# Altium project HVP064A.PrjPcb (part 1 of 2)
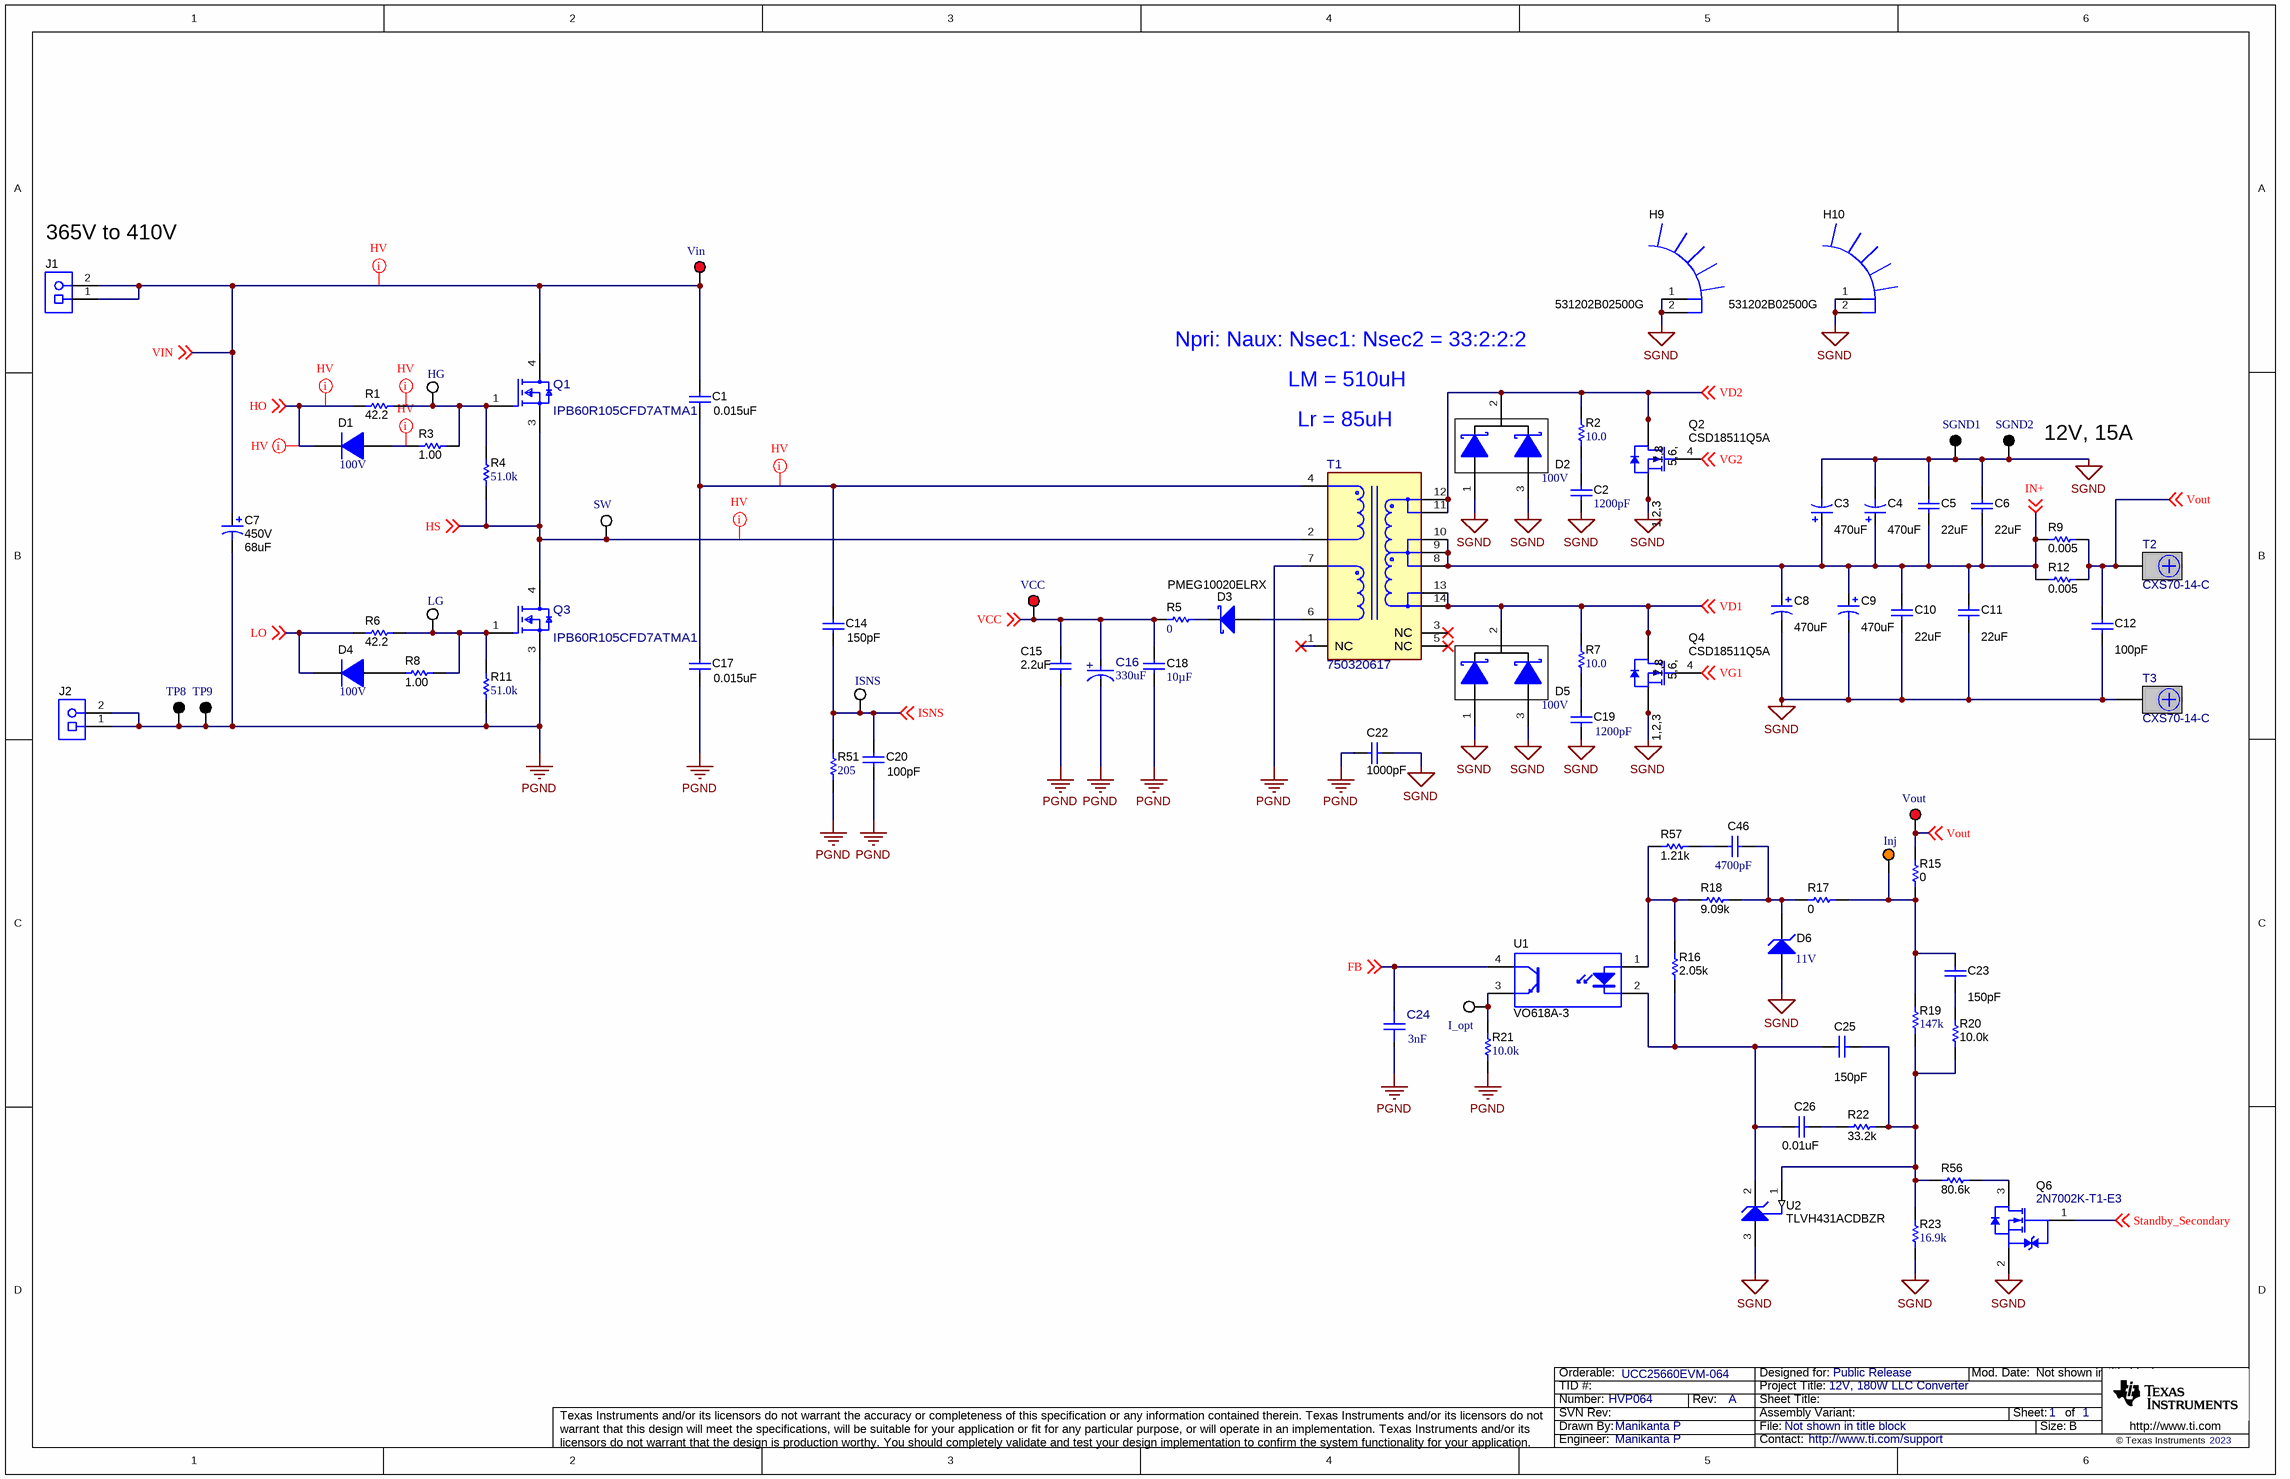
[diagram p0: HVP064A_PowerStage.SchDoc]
CopyrightYear: 2023; EVM_orderable: UCC25660EVM-064; PCB_Layout: Manikanta P; PCB_Rev: A; PRJ_Customer: Public Release; PRJ_Engineer: Manikanta P; PRJ_Number: HVP064; PRJ_Title: 12V, 180W LLC Converter; SCH_Rev: A; TechSupport: http://www.ti.com/support
3 sheets, 181 parts. Net scope: global (net labels, ports and power ports of the same name join across sheets).
Board file: HVP064A_PCB.PcbDoc
Sheets:
  HVP064A_PowerStage.SchDoc
  HVP064A_Control.SchDoc
  HVP064A_EVM_Hardware.SchDoc

## Sheet HVP064A_PowerStage.SchDoc
size 431 x 279 mm; EVM_orderable: UCC25660EVM-064; Date: Not shown in title block; ApprovedBy: Not shown in title block; CheckedBy: Not shown in title block; Author: Not shown in title block; CompanyName: Not shown in title block; DrawnBy: Manikanta P; Engineer: Not shown in title block; Organization: Not shown in title block; Address1: Not shown in title block; Address2: Not shown in title block; Address3: Not shown in title block; Address4: Not shown in title block; DocumentNumber: 1; Revision: Use project parameter SCH_Rev; SheetNumber: 1; SheetTotal: 1; PageSetup: Record=PageOptions¦CenterHorizontal=True¦CenterVertical=True¦PrintScale=1.00¦XCorrection=1.00¦YCorrection=1.00¦PrintKind=0¦BorderSize=5000000¦LeftOffset=0¦BottomOffset=0¦Orientation=2¦PaperLength=1000¦PaperWidth=1000¦Scale=100¦PaperSource=15¦PrintQuality=600¦MediaType=1¦DitherType=10¦PaperKind=Letter¦PrintScaleMode=1

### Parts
C1  ValueDisplayed: 0.015uF  [B32652_1800x700x1250]  (hidden comment: B32652A7153J000)
C2  ValueDisplayed: 1200pF  [0805L]  (hidden comment: GRM2165C2A122JA01D)
C3  ValueDisplayed: 470uF  [HW_1000x1600]  (hidden comment: UHW1V471MPD)
C4  ValueDisplayed: 470uF  [HW_1000x1600]  (hidden comment: UHW1V471MPD)
C5  ValueDisplayed: 22uF  [1206_190L]  (hidden comment: C3216X5R1E226M160AB)
C6  ValueDisplayed: 22uF  [1206_190L]  (hidden comment: C3216X5R1E226M160AB)
C7  VDC_V: 450V  ValueDisplayed: 68uF  [KXG_1800x3150]  (hidden comment: EKXG451ELL680MMN3S)
C8  ValueDisplayed: 470uF  [HW_1000x1600]  (hidden comment: UHW1V471MPD)
C9  ValueDisplayed: 470uF  [HW_1000x1600]  (hidden comment: UHW1V471MPD)
C10  ValueDisplayed: 22uF  [1206_190L]  (hidden comment: C3216X5R1E226M160AB)
C11  ValueDisplayed: 22uF  [1206_190L]  (hidden comment: C3216X5R1E226M160AB)
C12  ValueDisplayed: 100pF  [0603L]  (hidden comment: 06035A101FAT2A)
C14  ValueDisplayed: 150pF  [1206L]  (hidden comment: GRM31A5C2J151JW01D)
C15  ValueDisplayed: 2.2uF  [0805L]  (hidden comment: C2012X7R1V225K085AC)
C16  ValueDisplayed: 330uF  [FP-35ZL330MEFC10X16_RADIAL-MFG]  (hidden comment: 35ZL330MEFC10X16)
C17  ValueDisplayed: 0.015uF  [B32652_1800x700x1250]  (hidden comment: B32652A7153J000)
C18  ValueDisplayed: 10µF  [1206_180]  (hidden comment: C1206C106J3RACAUTO)
C19  ValueDisplayed: 1200pF  [0805L]  (hidden comment: GRM2165C2A122JA01D)
C20  ValueDisplayed: 100pF  [1206L]  (hidden comment: 12061A101JAT2A)
C22  ValueDisplayed: 1000pF  [CD45_700x600x1100]  (hidden comment: CD45-E2GA102M-NKA)
C23  ValueDisplayed: 150pF  [0402L]  (hidden comment: 885012005062)
C24  ValueDisplayed: 3nF  [FP-C1206C302J5GACTU_1206-MFG]  (hidden comment: C1206C302J5GACTU)
C25  ValueDisplayed: 150pF  [0402L]  (hidden comment: 885012005062)
C26  ValueDisplayed: 0.01uF  [0603L]  (hidden comment: 06031C103JAT2A)
C46  ValueDisplayed: 4700pF  [0603L]  (hidden comment: C0603C472J1GAC7867)
D1  Vr_V: 100V  [SOD-123]  (hidden comment: 1N4148W-7-F)
D2  Vr_V: 100V  [TO-220AB_100mil]  (hidden comment: STPS41H100CTY)
D3  PMEG10020ELRX  [SOD-123W]
D4  Vr_V: 100V  [SOD-123]  (hidden comment: 1N4148W-7-F)
D5  Vr_V: 100V  [TO-220AB_100mil]  (hidden comment: STPS41H100CTY)
D6  Vz_V: 11V  [SMA]  (hidden comment: 1SMA5926BT3G)
H9  531202B02500G  [531202]
H10  531202B02500G  [531202]
HG  5012  [Keystone5012]  (value not drawn)
I_opt  5012  [Keystone5012]  (value not drawn)
Inj  5013  [Keystone5013]  (value not drawn)
ISNS  5012  [Keystone5012]  (value not drawn)
J1  ED120/2DS  [On-Shore_ED120_2DS]  (value not drawn)
J2  ED120/2DS  [On-Shore_ED120_2DS]  (value not drawn)
LG  5012  [Keystone5012]  (value not drawn)
Q1  IPB60R105CFD7ATMA1  [FP-IPB60R105CFD7ATMA1_D2PAK-MFG]
Q2  CSD18511Q5A  [DQJ0008A]
Q3  IPB60R105CFD7ATMA1  [FP-IPB60R105CFD7ATMA1_D2PAK-MFG]
Q4  CSD18511Q5A  [DQJ0008A]
Q6  2N7002K-T1-E3  [SOT-23L]
R1  ValueDisplayed: 42.2  [0603]  (hidden comment: RC0603FR-0742R2L)
R2  ValueDisplayed: 10.0  [1206L]  (hidden comment: RC1206FR-0710RL)
R3  ValueDisplayed: 1.00  [0603L]  (hidden comment: RC0603FR-071RL)
R4  ValueDisplayed: 51.0k  [0603L]  (hidden comment: RC0603FR-0751KL)
R5  ValueDisplayed: 0  [1206L]  (hidden comment: ERJ-8GEY0R00V)
R6  ValueDisplayed: 42.2  [0603L]  (hidden comment: RC0603FR-0742R2L)
R7  ValueDisplayed: 10.0  [1206L]  (hidden comment: RC1206FR-0710RL)
R8  ValueDisplayed: 1.00  [0603L]  (hidden comment: RC0603FR-071RL)
R9  ValueDisplayed: 0.005  [2010L]  (hidden comment: CSNL2010FT5L00)
R11  ValueDisplayed: 51.0k  [0603L]  (hidden comment: RC0603FR-0751KL)
R12  ValueDisplayed: 0.005  [2010L]  (hidden comment: CSNL2010FT5L00)
R15  ValueDisplayed: 0  [0402L]  (hidden comment: RC0402JR-070RL)
R16  ValueDisplayed: 2.05k  [0603L]  (hidden comment: RC0603FR-072K05L)
R17  ValueDisplayed: 0  [1206L]  (hidden comment: CRCW12060000Z0EAHP)
R18  ValueDisplayed: 9.09k  [0603L]  (hidden comment: RC0603FR-079K09L)
R19  ValueDisplayed: 147k  [0603L]  (hidden comment: RC0603FR-07147KL)
R20  ValueDisplayed: 10.0k  [0603L]  (hidden comment: ERJ-3EKF1002V)
R21  ValueDisplayed: 10.0k  [0402L]  (hidden comment: ERJ-2RKF1002X)
R22  ValueDisplayed: 33.2k  [0603L]  (hidden comment: RC0603FR-0733K2L)
R23  ValueDisplayed: 16.9k  [0603L]  (hidden comment: RC0603FR-0716K9L)
R51  ValueDisplayed: 205  [1206]  (hidden comment: RC1206FR-07205RL)
R56  ValueDisplayed: 80.6k  [0603L]  (hidden comment: RC0603FR-0780K6L)
R57  ValueDisplayed: 1.21k  [0603L]  (hidden comment: RC0603FR-071K21L)
SGND1  5011  [Keystone5011]  (value not drawn)
SGND2  5011  [Keystone5011]  (value not drawn)
SW  5012  [Keystone5012]  (value not drawn)
T1  750320617  [FP-750320617_PTH_XFRMR_36MM5_43MM0-MFG]
T2  CXS70-14-C  [Panduit_CXS70-14-C]
T3  CXS70-14-C  [Panduit_CXS70-14-C]
TP8  5011  [Keystone5011]  (value not drawn)
TP9  5011  [Keystone5011]  (value not drawn)
U1  VO618A-3  [DIP-4]
U2  TLVH431ACDBZR  [DBZ0003A_N]
VCC  5010  [Keystone5010]  (value not drawn)
Vin  5010  [Keystone5010]  (value not drawn)
Vout  5010  [Keystone5010]  (value not drawn)

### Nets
PGND: C7.2(-) C15.2 C16.1(CATHODE) C17.2 C18.2 C20.2 C22.2 C24.2 J2.1 J2.2 Q3.3(Source) R11.1 R21.1 R51.1 T1.7 TP8.1 TP9.1
SGND: C2.2 C3.2(-) C4.2(-) C5.1 C6.1 C8.2(-) C9.2(-) C10.2 C11.2 C12.2 C19.2 C22.1 D2.1(A) D2.3(A) D5.1(A) D5.3(A) D6.2(A) H9.1 H9.2 H10.1 H10.2 Q2.1(S) Q2.2(S) Q2.3(S) Q4.1(S) Q4.2(S) Q4.3(S) Q6.2(S) R23.1 SGND1.1 SGND2.1 T3.1 U2.3(ANODE)
FB: C24.1 U1.4(C) ; off-sheet FB
HO: D1.1(K) R1.1 ; off-sheet HO
HS: Q1.3(Source) Q3.4(Drain) R4.1 SW.1 T1.2 ; off-sheet HS
IN+: C3.1(+) C4.1(+) C5.2 C6.2 C8.1(+) C9.1(+) C10.1 C11.1 R9.1 R12.1 T1.8 T1.9 T1.10 ; off-sheet IN+
ISNS: C14.2 C20.1 ISNS.1 R51.2 ; off-sheet ISNS
LO: D4.1(K) R6.1 ; off-sheet LO
Standby_Secondary: Q6.1(G) ; off-sheet Standby_Secondary
VCC: C15.1 C16.2(ANODE) C18.1 R5.1 VCC.1 ; off-sheet VCC
VD1: D5.2(K) Q4.5(D) Q4.6(D) Q4.7(D) Q4.8(D) Q4.9(D) R7.2 T1.13 T1.14 ; off-sheet VD1
VD2: D2.2(K) Q2.5(D) Q2.6(D) Q2.7(D) Q2.8(D) Q2.9(D) R2.2 T1.11 T1.12 ; off-sheet VD2
VG1: Q4.4(G) ; off-sheet VG1
VG2: Q2.4(G) ; off-sheet VG2
VIN: C1.1 C7.1(+) J1.1 J1.2 Q1.4(Drain) Vin.1 ; off-sheet VIN
Vout: C12.1 R9.2 R12.2 R15.2 T2.1 Vout.1 ; off-sheet Vout
NetC1_2: C1.2 C14.1 C17.1 T1.4
NetC2_1: C2.1 R2.1
NetC19_1: C19.1 R7.1
NetC23_1: C23.1 Inj.1 R15.1 R17.2 R19.2
NetC23_2: C23.2 R20.2
NetC25_1: C25.1 R19.1 R20.1 R22.1 R23.2 R56.1 U2.1(REF)
NetC25_2: C25.2 C26.2 R16.1 U1.2(K) U2.2(CATHODE)
NetC26_1: C26.1 R22.2
NetC46_1: C46.1 D6.1(K) R17.1 R18.2
NetC46_2: C46.2 R57.2
NetD1_2: D1.2(A) R3.1
NetD3_1: D3.1(K) R5.2
NetD3_2: D3.2(A) T1.6
NetD4_2: D4.2(A) R8.1
NetHG_1: HG.1 Q1.1(Gate) R1.2 R3.2 R4.2
NetI_opt_1: I_opt.1 R21.2 U1.3(E)
NetLG_1: LG.1 Q3.1(Gate) R6.2 R8.2 R11.2
NetQ6_3: Q6.3(D) R56.2
NetR16_2: R16.2 R18.1 R57.1 U1.1(A)

Not connected (* = marked no-connect by the designer): T1 1(NC)* 3(NC)* 5(NC)*

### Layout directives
net class HV: HO, HS, NetC1_2, NetD1_2, NetHG_1, VIN

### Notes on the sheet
- (near J1) 365V to 410V
- Npri: Naux: Nsec1: Nsec2 = 33:2:2:2
- Lr = 85uH
- LM = 510uH
- (near SGND2) 12V, 15A

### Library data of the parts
C1 C17 = CMP-0012346-3: CAP, Film, 0.015 uF, 1250 V, +/- 5%, AEC-Q200 Grade 3, TH; Manufacturer: TDK; TaMin_C: -55°C; Polarized: N; SizeAreaWB_mm2: 180; Value1: Unknown; TaMax_C: 100°C; SizeZ_mm: 12.5; SizeX_mm: 18; SizeY_mm: 7; Cap_Case: 18x7x12.5; Value2: 1250V; SizeArea_mm2: 126; CompType: Capacitor; AEC Qualified: Y; Cap_F: 15nF; VDC_V: 1.25kV; AEC Grade: 3; AEC Category: Q200
C2 C19 = CMP-0008098-2: CAP, CERM, 1200 pF, 100 V, +/- 5%, C0G/NP0, 0805; Manufacturer: MuRata; TaMin_C: -55°C; Polarized: N; SizeAreaWB_mm2: 6.75; Value1: Unknown; U/M: EA; Value: 1200pF; TaMax_C: 125°C; SizeZ_mm: 1.45; SizeX_mm: 2; SizeY_mm: 1.25; Cap_Case: 0805; Value2: 100V; SizeArea_mm2: 2.5; Cap_F: 1.2nF; AEC Category: Q200
C3 C4 C8 C9 = CMP-0010541-2: CAP, AL, 470 uF, 35 V, +/- 20%, 0.03 ohm, TH; Manufacturer: Nichicon; TaMin_C: -40°C; ESR_ohm: 0.03; Polarized: Y; SizeAreaWB_mm2: 144; U/M: EA; Value: 470uF; TaMax_C: 105°C; SizeZ_mm: 17.5; SizeX_mm: 10; Cap_Case: 10x16mm; Value2: 35V; SizeArea_mm2: 100; CompType: Capacitor; AEC Qualified: N; Cap_F: 470µF; IRMS_A: 2A; AEC Category: Q200
C5 C6 C10 C11 = CMP-0008654-2: CAP, CERM, 22 uF, 25 V, +/- 20%, X5R, 1206_190; Manufacturer: TDK; TaMin_C: -55°C; Polarized: N; SizeAreaWB_mm2: 10.92; Value1: Unknown; U/M: EA; Value: 22uF; TaMax_C: 85°C; SizeZ_mm: 1.9; SizeX_mm: 3.2; SizeY_mm: 1.6; Cap_Case: 1206; Value2: 25V; SizeArea_mm2: 5.12; CompType: Capacitor; Cap_F: 22µF; AEC Category: Q200
C7 = CMP-0010043-2: CAP, AL, 68 uF, 450 V, +/- 20%, TH; Manufacturer: Chemi-Con; TaMin_C: -25°C; Polarized: Y; SizeAreaWB_mm2: 400; Value1: Unknown; U/M: EA; Value: 68uF; TaMax_C: 105°C; SizeZ_mm: 33; SizeX_mm: 18; Cap_Case: 18x31.5mm; SizeArea_mm2: 324; CompType: Capacitor; Cap_F: 68µF; IRMS_A: 6.3dA; AEC Category: Q200
C12 = CMP-0006762-4: CAP, CERM, 100 pF, 50 V, +/- 1%, C0G/NP0, 0603; Manufacturer: AVX; TaMin_C: -55°C; Polarized: N; SizeAreaWB_mm2: 4.68; Value1: Unknown; U/M: EA; TaMax_C: 125°C; SizeZ_mm: 1; SizeX_mm: 1.6; SizeY_mm: 0.8; Cap_Case: 0603; Value2: 50V; SizeArea_mm2: 1.28; CompType: Capacitor; Value: 100pF; AEC Category: Q200
C14 = CMP-0008885-2: CAP, CERM, 150 pF, 630 V, +/- 5%, C0G/NP0, 1206; Manufacturer: MuRata; TaMin_C: -55°C; Polarized: N; SizeAreaWB_mm2: 10.92; Value1: Unknown; U/M: EA; Value: 150pF; TaMax_C: 125°C; SizeZ_mm: 1.35; SizeX_mm: 3.2; SizeY_mm: 1.6; Cap_Case: 1206; Value2: 630V; SizeArea_mm2: 5.12; CompType: Capacitor; AEC Category: Q200
C15 = CMP-0007883-2: CAP, CERM, 2.2 uF, 35 V, +/- 10%, X7R, 0805; Manufacturer: TDK; TaMin_C: -55°C; Polarized: N; SizeAreaWB_mm2: 6.75; Value1: Unknown; U/M: EA; Value: 2.2uF; TaMax_C: 125°C; SizeZ_mm: 1.45; SizeX_mm: 2; SizeY_mm: 1.25; Cap_Case: 0805; Value2: 35V; SizeArea_mm2: 2.5; CompType: Capacitor; Cap_F: 2.2µF; AEC Category: Q200
C16 = CMP-0098283-1: Cap Aluminum Lytic 330uF 35V 20% (10 X 16mm) Radial 5mm 1430mA 4000h 105C Bulk; Manufacturer: Rubycon; AEC Qualified: No; Cap_F: 330µF; IRMS_A: 1.43A; SizeZ_mm: 17.5mm; Dissipation Factor: 12%; Leakage Current: 115.5uA; Life: 4000Hours; Value: 330µF
C18 = CMP-0081062-1: CAP, CERM, 10 µF, 25 V,+/- 5%, X7R, AEC-Q200 Grade 1, 1206; Manufacturer: Kemet; TaMin_C: -55°C; Polarized: N; SizeAreaWB_mm2: 10.92; U/M: EA; Value: 10uF; TaMax_C: 125°C; SizeZ_mm: 1.8; SizeX_mm: 3.2; SizeY_mm: 1.6; Value2: 25V; SizeArea_mm2: 5.12; AEC Qualified: Y; AEC Grade: 1; AEC Category: Q200
C20 = CMP-0008462-2: CAP, CERM, 100 pF, 100 V, +/- 5%, C0G/NP0, 1206; Manufacturer: AVX; TaMin_C: -55°C; ESR_ohm: 7.01d; Polarized: N; SizeAreaWB_mm2: 10.92; Value1: 0.701 ohm; U/M: EA; Value: 100pF; TaMax_C: 125°C; SizeZ_mm: 1.35; SizeX_mm: 3.2; SizeY_mm: 1.6; Cap_Case: 1206; Value2: 100V; SizeArea_mm2: 5.12; CompType: Capacitor; AEC Category: Q200
C22 = CMP-0009595-2: CAP, CERM, 1000 pF,  V, +/- 20%, E, D7xT6mm; Manufacturer: TDK; TaMin_C: -25°C; Polarized: N; SizeAreaWB_mm2: 101.2; Value1: Unknown; U/M: EA; Value: 1000pF; TaMax_C: 125°C; SizeZ_mm: 11; SizeX_mm: 10.65; SizeY_mm: 6; Cap_Case: 7x6x11mm; SizeArea_mm2: 63.9; Cap_F: 1nF; AEC Category: Q200
C23 C25 = CMP-0064913-2: CAP, CERM, 150 pF, 50 V,+/- 5%, C0G/NP0, 0402; Manufacturer: Wurth Elektronik; TaMin_C: -55°C; Polarized: N; SizeAreaWB_mm2: 3; Value1: Unknown; U/M: EA; Value: 150pF; TaMax_C: 125°C; SizeZ_mm: 0.6; SizeX_mm: 1; SizeY_mm: 0.5; Cap_Case: 0402; Value2: 50V; CompType: Capacitor; AEC Category: Q200
C24 = CMP-0120451-1: C1206 3,000 pF C0G 5.00% 50 V; Manufacturer: KEMET; AEC Grade: Grade 0; AEC Qualified: Yes; Cap_F: 3pF; SizeZ_mm: 0.88mm; TempCo: 15%; Tolerance_%: 0.05%; VDC_V: 50V; Value: 3pF
C26 = CMP-0006726-4: CAP, CERM, 0.01 uF, 100 V, +/- 5%, X7R, 0603; Manufacturer: AVX; TaMin_C: -55°C; ESR_ohm: 0.098; Polarized: N; SizeAreaWB_mm2: 4.68; Value1: 0.098 ohm; U/M: EA; Value: 0.01uF; TaMax_C: 125°C; SizeZ_mm: 1; SizeX_mm: 1.6; SizeY_mm: 0.8; Cap_Case: 0603; Value2: 100V; SizeArea_mm2: 1.28; Cap_F: 10nF; AEC Category: Q200
C46 = CMP-0006941-4: CAP, CERM, 4700 pF, 100 V, +/- 5%, C0G/NP0, 0603; Manufacturer: Kemet; TaMin_C: -55°C; Polarized: N; SizeAreaWB_mm2: 4.68; Value1: Unknown; U/M: EA; Value: 4700pF; TaMax_C: 125°C; SizeZ_mm: 1; SizeX_mm: 1.6; SizeY_mm: 0.8; Cap_Case: 0603; Value2: 100V; SizeArea_mm2: 1.28; Cap_F: 4.7nF; AEC Category: Q200
D1 D4 = CMP-0029001-2: Diode, Ultrafast, 100 V, 0.15 A, SOD-123; Manufacturer: Diodes Inc.; Io_A: 150mA; Green_Lifecycle: Active; SizeAreaWB_mm2: 13.095; Green_REACh: Passed; Value1: 0.15A; TJmax_C: 150°C; Value: 100V; SizeZ_mm: 1.35; SizeX_mm: 3.85; SizeY_mm: 1.7; Vf_V: 1.25V; SizeArea_mm2: 6.545; AEC Category: Q101
D2 D5 = CMP-0028866-3: Diode, Schottky, 100 V, 20 A, AEC-Q101, TH; Manufacturer: STMicroelectronics; Io_A: 20A; Green_Lifecycle: Not Set; SizeAreaWB_mm2: 79.3; Green_REACh: Incomplete; TJmax_C: 175°C; Value: 100V; SizeZ_mm: 19.4; SizeX_mm: 10.2; SizeY_mm: 4.5; Vf_V: 800mV; Value2: 0.8V; SizeArea_mm2: 45.9; AEC Qualified: Y; AEC Category: Q101
D3 = CMP-0028977-2: Diode, Schottky, 100 V, 2 A, AEC-Q101, SOD-123W; Manufacturer: Nexperia; Io_A: 2A; SizeAreaWB_mm2: 12.15; Vr_V: 100V; TJmax_C: 175°C; Value: 100V; SizeZ_mm: 1; SizeX_mm: 3.5; SizeY_mm: 1.7; Vf_V: 830mV; Value2: 0.83V; SizeArea_mm2: 5.95; AEC Qualified: Y; AEC Category: Q101
D6 = CMP-0005522-4: Diode, Zener, 11 V, 1.5 W, SMA; Manufacturer: ON Semiconductor; Power_W: 1.5W; SizeAreaWB_mm2: 37.3428; RJA_CperW: 250; Value: 11V; SizeZ_mm: 2.87; SizeX_mm: 5.59; SizeY_mm: 2.92; SizeArea_mm2: 16.3228; AEC Category: Q101
H9 H10 = CMP-0004053-1: Manufacturer: Aavid; Note: footprint renamed from HSINK_531202B025B025 to 531202; CompType: Heat Sink
HG I_opt ISNS LG SW = CMP-0055149-2: Test Point, Multipurpose, White, TH; Manufacturer: Keystone Electronics; CNHeader: FALSE; Green_Lifecycle: Active; Green_REACh: Passed; ContactFinish: Silver; CT: TRUE
Inj = CMP-0055150-2: Test Point, Multipurpose, Orange, TH; Manufacturer: Keystone Electronics; CNHeader: FALSE; Green_Lifecycle: Active; Green_REACh: Passed; ContactFinish: Silver; CT: TRUE
J1 J2 = CMP-0074910-1: Terminal Block, 5.08 mm, 2x1, Brass, TH; Manufacturer: On-Shore Technology; Cert_VDE: Y; CNHeader: False; Current_A: 15A; Green_Lifecycle: Not Set; Shrouded: N; Gender: Female; Green_REACh: Incomplete; Voltage_V: 300V; Row_Count: 1; Pitch_mm: 5.08; CT: True
Q1 Q3 = CMP-0065576-1: Power Transistor MOSFET N-Channel Enhancement 600V 21A 3-Pin D2PAK T/R; Manufacturer: Infineon; AEC Qualified: No; QgTyp_nC: 42nC @ 10V; Rdson45_ohm: 89m; SizeZ_mm: 4.5mm; Vgs_V: 20V; ChMode: False; Input Capacitace At Vds: 1752pF @ 400V; Number Of Channels: 1; Power_W: 106W; Pulse Drain Current: 79A; Reverse Recovery Charge: 480nC; Reverse Recovery Time: 102ns; Rthja Max: 62°C/W; Standoff Height: 0.1mm; Threshold Vgs Max: 4.5V; Threshold Vgs Min: 3.5V; TJmax_C: +150°C; Turn Off Delay Time: 94ns; Turn On Delay Time: 25ns; Typ Forward Diode Voltage: 1V
Q2 Q4 = CMP-0000711-1: MOSFET, N-CH, 40 V, 100 A, DQJ0008A (VSONP-8); Alternate Manufacturer: None; Manufacturer: Texas Instruments; SizeZ_mm: 1.1; ChType: N; Value2: 63 nC; Value1: 0.003; VdsMax_V: 40V; SizeX_mm: 6; SizeY_mm: 4.9; Vgs_V: 20V; Value: 40V; Rdson45_ohm: 3.5m; SizeArea_mm2: 29.4; AEC Category: Q101; IdsMax_A: 100A; SizeAreaWB_mm2: 55.2; U/M: EA; QgTyp_nC: 63
Q6 = CMP-0000773-1: MOSFET, N-CH, 60 V, 0.3 A, SOT-23; Alternate Manufacturer: None; Manufacturer: Vishay-Siliconix; SizeZ_mm: 1.1; ChType: N; Value2: 0.4 nC; VdsMax_V: 60V; SizeX_mm: 2.5; SizeY_mm: 3; Vgs_V: 20V; Value: 60V; Rdson45_ohm: 4; SizeArea_mm2: 7.5; AEC Category: Q101; IdsMax_A: 300mA; SizeAreaWB_mm2: 14; U/M: EA; QgTyp_nC: 0.4
R1 R6 = CMP-0023107-5: RES, 42.2, 1%, 0.1 W, 0603; Manufacturer: Yageo; Power_W: 100mW; TempCo: 100 ppm/C; Value_Code: 42R2; Value: 42.2; EIA_Code: E96; SizeX_mm: 1.6; SizeY_mm: 0.8; SizeZ_mm: 1; Value2: 0.1W; SizeArea_mm2: 1.28; CompType: Resistor; AEC Qualified: N; VDC_V: 75V; AEC Category: Q200; SizeAreaWB_mm2: 4.68
R2 R7 = CMP-0017851-2: RES, 10.0, 1%, 0.25 W, 1206; Manufacturer: Yageo America; Power_W: 250mW; TempCo: 200 ppm/C; Value_Code: 10R0; U/M: EA; Value: 10.0; EIA_Code: E96; Res_ohm: 10; SizeX_mm: 3.2; SizeY_mm: 1.6; SizeZ_mm: 1.35; Value2: 0.25W; SizeArea_mm2: 5.12; VDC_V: 200V; AEC Category: Q200
R3 R8 = CMP-0022900-4: RES, 1.00, 1%, 0.1 W, 0603; Manufacturer: Yageo; Power_W: 100mW; TempCo: 200 ppm/C; Value_Code: 1R00; Value: 1.00; EIA_Code: E96; Res_ohm: 1; SizeX_mm: 1.6; SizeY_mm: 0.8; Value2: 0.1W; SizeArea_mm2: 1.28; CompType: Resistor; AEC Qualified: N; VDC_V: 75V; AEC Category: Q200; SizeAreaWB_mm2: 4.68
R4 R11 = CMP-0023167-5: RES, 51.0 k, 1%, 0.1 W, 0603; Manufacturer: Yageo; Power_W: 100mW; TempCo: 100 ppm/C; Value_Code: 51k0; Value: 51.0k; Res_ohm: 51k; SizeX_mm: 1.6; SizeY_mm: 0.8; SizeZ_mm: 1; Value2: 0.1W; SizeArea_mm2: 1.28; AEC Qualified: N; VDC_V: 75V; AEC Category: Q200; SizeAreaWB_mm2: 4.68
R5 = CMP-0018748-3: RES, 0, 5%, 0.25 W, AEC-Q200 Grade 0, 1206; Manufacturer: Panasonic; Power_W: 250mW; TempCo: 600 ppm/C; Value_Code: 0000; Value: 0; EIA_Code: E24; SizeX_mm: 3.2; SizeY_mm: 1.6; SizeZ_mm: 1.35; Value2: 0.25W; SizeArea_mm2: 5.12; AEC Qualified: Y; VDC_V: 200V; AEC Category: Q200; SizeAreaWB_mm2: 10.92
R9 R12 = CMP-0016512-2: RES, 0.005, 1%, 1.5 W, 2010; Manufacturer: Stackpole Electronics Inc; Power_W: 1.5W; TempCo: 50 ppm/C; Value_Code: 5L000; U/M: EA; Value: 0.005; EIA_Code: E96; Res_ohm: 5m; SizeX_mm: 5; SizeY_mm: 2.5; SizeZ_mm: 1.66; SizeArea_mm2: 12.5; CompType: Resistor; AEC Category: Q200
R15 = CMP-0027004-2: RES, 0, 5%, 0.063 W, 0402; Manufacturer: Yageo America; Power_W: 63mW; TempCo: 200 ppm/C; Value_Code: 0000; U/M: EA; Value: 0; EIA_Code: E24; SizeX_mm: 1; SizeY_mm: 0.5; SizeZ_mm: 0.6; Value2: 0.063W; CompType: Resistor; VDC_V: 50V; AEC Category: Q200
R16 = CMP-0022981-5: RES, 2.05 k, 1%, 0.1 W, 0603; Manufacturer: Yageo; Power_W: 100mW; TempCo: 100 ppm/C; Value_Code: 2k05; Value: 2.05k; EIA_Code: E96; SizeX_mm: 1.6; SizeY_mm: 0.8; SizeZ_mm: 1; Value2: 0.1W; SizeArea_mm2: 1.28; AEC Qualified: N; VDC_V: 75V; AEC Category: Q200; SizeAreaWB_mm2: 4.68
R17 = CMP-0086176-1: RES, 0, 0.75 W, AEC-Q200 Grade 0, 1206; Manufacturer: Vishay-Dale; Value: 0; SizeY_mm: 1.6; SizeX_mm: 3.2; Tolerance_%: 0%; SizeArea_mm2: 5.12; EIA_Code: E96; SizeAreaWB_mm2: 10.92; Power_W: 750mW; AEC Qualified: Y; SizeZ_mm: 1.35; Value2: 0.75W; AEC Category: Q200; VDC_V: 200V
R18 = CMP-0023332-5: RES, 9.09 k, 1%, 0.1 W, 0603; Manufacturer: Yageo; Power_W: 100mW; TempCo: 100 ppm/C; Value_Code: 9k09; Value: 9.09k; EIA_Code: E96; SizeX_mm: 1.6; SizeY_mm: 0.8; SizeZ_mm: 1; Value2: 0.1W; SizeArea_mm2: 1.28; AEC Qualified: N; VDC_V: 75V; AEC Category: Q200; SizeAreaWB_mm2: 4.68
R19 = CMP-0022800-4: RES, 147 k, 1%, 0.1 W, 0603; Manufacturer: Yageo; Power_W: 100mW; TempCo: 100 ppm/C; Value: 147k; EIA_Code: E96; SizeX_mm: 1.6; SizeY_mm: 0.8; SizeZ_mm: 1; Value2: 0.1W; SizeArea_mm2: 1.28; AEC Qualified: N; VDC_V: 75V; AEC Category: Q200; SizeAreaWB_mm2: 4.68
R20 = CMP-0022684-3: RES, 10.0 k, 1%, 0.1 W, 0603; Manufacturer: Panasonic; Power_W: 100mW; TempCo: 100 ppm/C; Value_Code: 10k0; U/M: EA; Value: 10.0k; EIA_Code: E96; Res_ohm: 10k; SizeX_mm: 1.6; SizeY_mm: 0.8; SizeZ_mm: 1; Value2: 0.1W; SizeArea_mm2: 1.28; CompType: Resistor; VDC_V: 75V; AEC Category: Q200
R21 = CMP-0026658-1: RES, 10.0 k, 1%, 0.1 W, 0402; Manufacturer: Panasonic; Power_W: 100mW; TempCo: 100 ppm/C; Value_Code: 10k0; U/M: EA; Value: 10.0k; EIA_Code: E96; Res_ohm: 10k; SizeX_mm: 1; SizeY_mm: 0.5; SizeZ_mm: 0.6; Value2: 0.1W; VDC_V: 50V; AEC Category: Q200
R22 = CMP-0023036-5: RES, 33.2 k, 1%, 0.1 W, 0603; Manufacturer: Yageo; Power_W: 100mW; TempCo: 100 ppm/C; Value_Code: 33k2; Value: 33.2k; EIA_Code: E96; SizeX_mm: 1.6; SizeY_mm: 0.8; SizeZ_mm: 1; Value2: 0.1W; SizeArea_mm2: 1.28; AEC Qualified: N; VDC_V: 75V; AEC Category: Q200; SizeAreaWB_mm2: 4.68
R23 = CMP-0022830-5: RES, 16.9 k, 1%, 0.1 W, 0603; Manufacturer: Yageo; Power_W: 100mW; TempCo: 100 ppm/C; Value_Code: 16k9; Value: 16.9k; EIA_Code: E96; SizeX_mm: 1.6; SizeY_mm: 0.8; SizeZ_mm: 1; Value2: 0.1W; SizeArea_mm2: 1.28; AEC Qualified: N; VDC_V: 75V; AEC Category: Q200; SizeAreaWB_mm2: 4.68
R51 = CMP-0018063-2: RES, 205, 1%, 0.25 W, 1206; Manufacturer: Yageo America; Power_W: 250mW; TempCo: 100 ppm/C; Value_Code: 205R; U/M: EA; Value: 205; EIA_Code: E96; SizeX_mm: 3.2; SizeY_mm: 1.6; SizeZ_mm: 1.35; Value2: 0.25W; SizeArea_mm2: 5.12; VDC_V: 200V; AEC Category: Q200
R56 = CMP-0023285-5: RES, 80.6 k, 1%, 0.1 W, 0603; Manufacturer: Yageo; Power_W: 100mW; TempCo: 100 ppm/C; Value_Code: 80k6; EIA_Code: E96; SizeX_mm: 1.6; SizeY_mm: 0.8; SizeZ_mm: 1; Value2: 0.1W; Value: 80.6k; SizeArea_mm2: 1.28; AEC Qualified: N; VDC_V: 75V; AEC Category: Q200; SizeAreaWB_mm2: 4.68
R57 = CMP-0022871-5: RES, 1.21 k, 1%, 0.1 W, 0603; Manufacturer: Yageo; Power_W: 100mW; TempCo: 100 ppm/C; Value_Code: 1k21; Value: 1.21k; EIA_Code: E96; SizeX_mm: 1.6; SizeY_mm: 0.8; SizeZ_mm: 1; Value2: 0.1W; SizeArea_mm2: 1.28; AEC Qualified: N; VDC_V: 75V; AEC Category: Q200; SizeAreaWB_mm2: 4.68
SGND1 SGND2 TP8 TP9 = CMP-0055148-2: Test Point, Multipurpose, Black, TH; Manufacturer: Keystone Electronics; CNHeader: FALSE; Green_Lifecycle: Active; Green_REACh: Passed; ContactFinish: Silver; CT: TRUE
T1 = CMP-0065589-1: TRANSFORMER-; Manufacturer: Wurth Electronics; DCR_ohm: 0.135; Ind_H: 510µH; Ns1toNp: 16.5:1; Rsec1_ohm: 5m; SizeZ_mm: 26.5mm; AEC Qualified: No; Frequency_Fixed: 60-130kHz; Voltage_Isolation_Vrms: 3kV
T2 T3 = CMP-0075010-2: Terminal 70A Lug; Manufacturer: Panduit; CNHeader: False; Green_Lifecycle: Not Set; Green_REACh: Incomplete; CompType: Screw Terminal
U1 = CMP-0083653-1: Optocoupler, 5.3 kV, 100-200% CTR, SMT; Manufacturer: Vishay-Semiconductor; CTR (Max): 200%; SizeAreaWB_mm2: 71.064; CTR (Min): 100%; SizeZ_mm: 5; SizeX_mm: 8.8; SizeY_mm: 4.58; SizeArea_mm2: 40.304; Voltage_Isolation_Vrms: 5.3kV
U2 = CMP-0033066-1: Low-Voltage Adjustable Precision Shunt Regulator, 129 ppm / degC, 80 mA, 0 to 70 degC, 3-pin SOT-23 (DBZ), Green (RoHS & no Sb/Br); Manufacturer: Texas Instruments; Min Iz for Regulation(uA): 80; VO Adj(Max)(V): 18; VO Adj(Min)(V): 1.24; Rating: Catalog; SubFamily: Shunt Voltage Reference; Temp Coeff(Max)(ppm/ degree C): 129
VCC Vin Vout = CMP-0055147-2: Test Point, Multipurpose, Red, TH; Manufacturer: Keystone Electronics; CNHeader: FALSE; Green_Lifecycle: Active; Green_REACh: Passed; ContactFinish: Silver; CT: TRUE

## Sheet HVP064A_Control.SchDoc
size 431 x 279 mm; Date: Not shown in title block; ApprovedBy: Not shown in title block; CheckedBy: Not shown in title block; Author: Not shown in title block; CompanyName: Not shown in title block; Engineer: Not shown in title block; Organization: Not shown in title block; Address1: Not shown in title block; Address2: Not shown in title block; Address3: Not shown in title block; Address4: Not shown in title block; DocumentNumber: 1; Revision: Use project parameter SCH_Rev; SheetNumber: 1; SheetTotal: 1; PageSetup: Record=PageOptions¦CenterHorizontal=True¦CenterVertical=True¦PrintScale=1.00¦XCorrection=1.00¦YCorrection=1.00¦PrintKind=0¦BorderSize=5000000¦LeftOffset=0¦BottomOffset=0¦Orientation=2¦PaperLength=1000¦PaperWidth=1000¦Scale=100¦PaperSource=15¦PrintQuality=600¦MediaType=1¦DitherType=10¦PaperKind=Letter¦PrintScaleMode=1
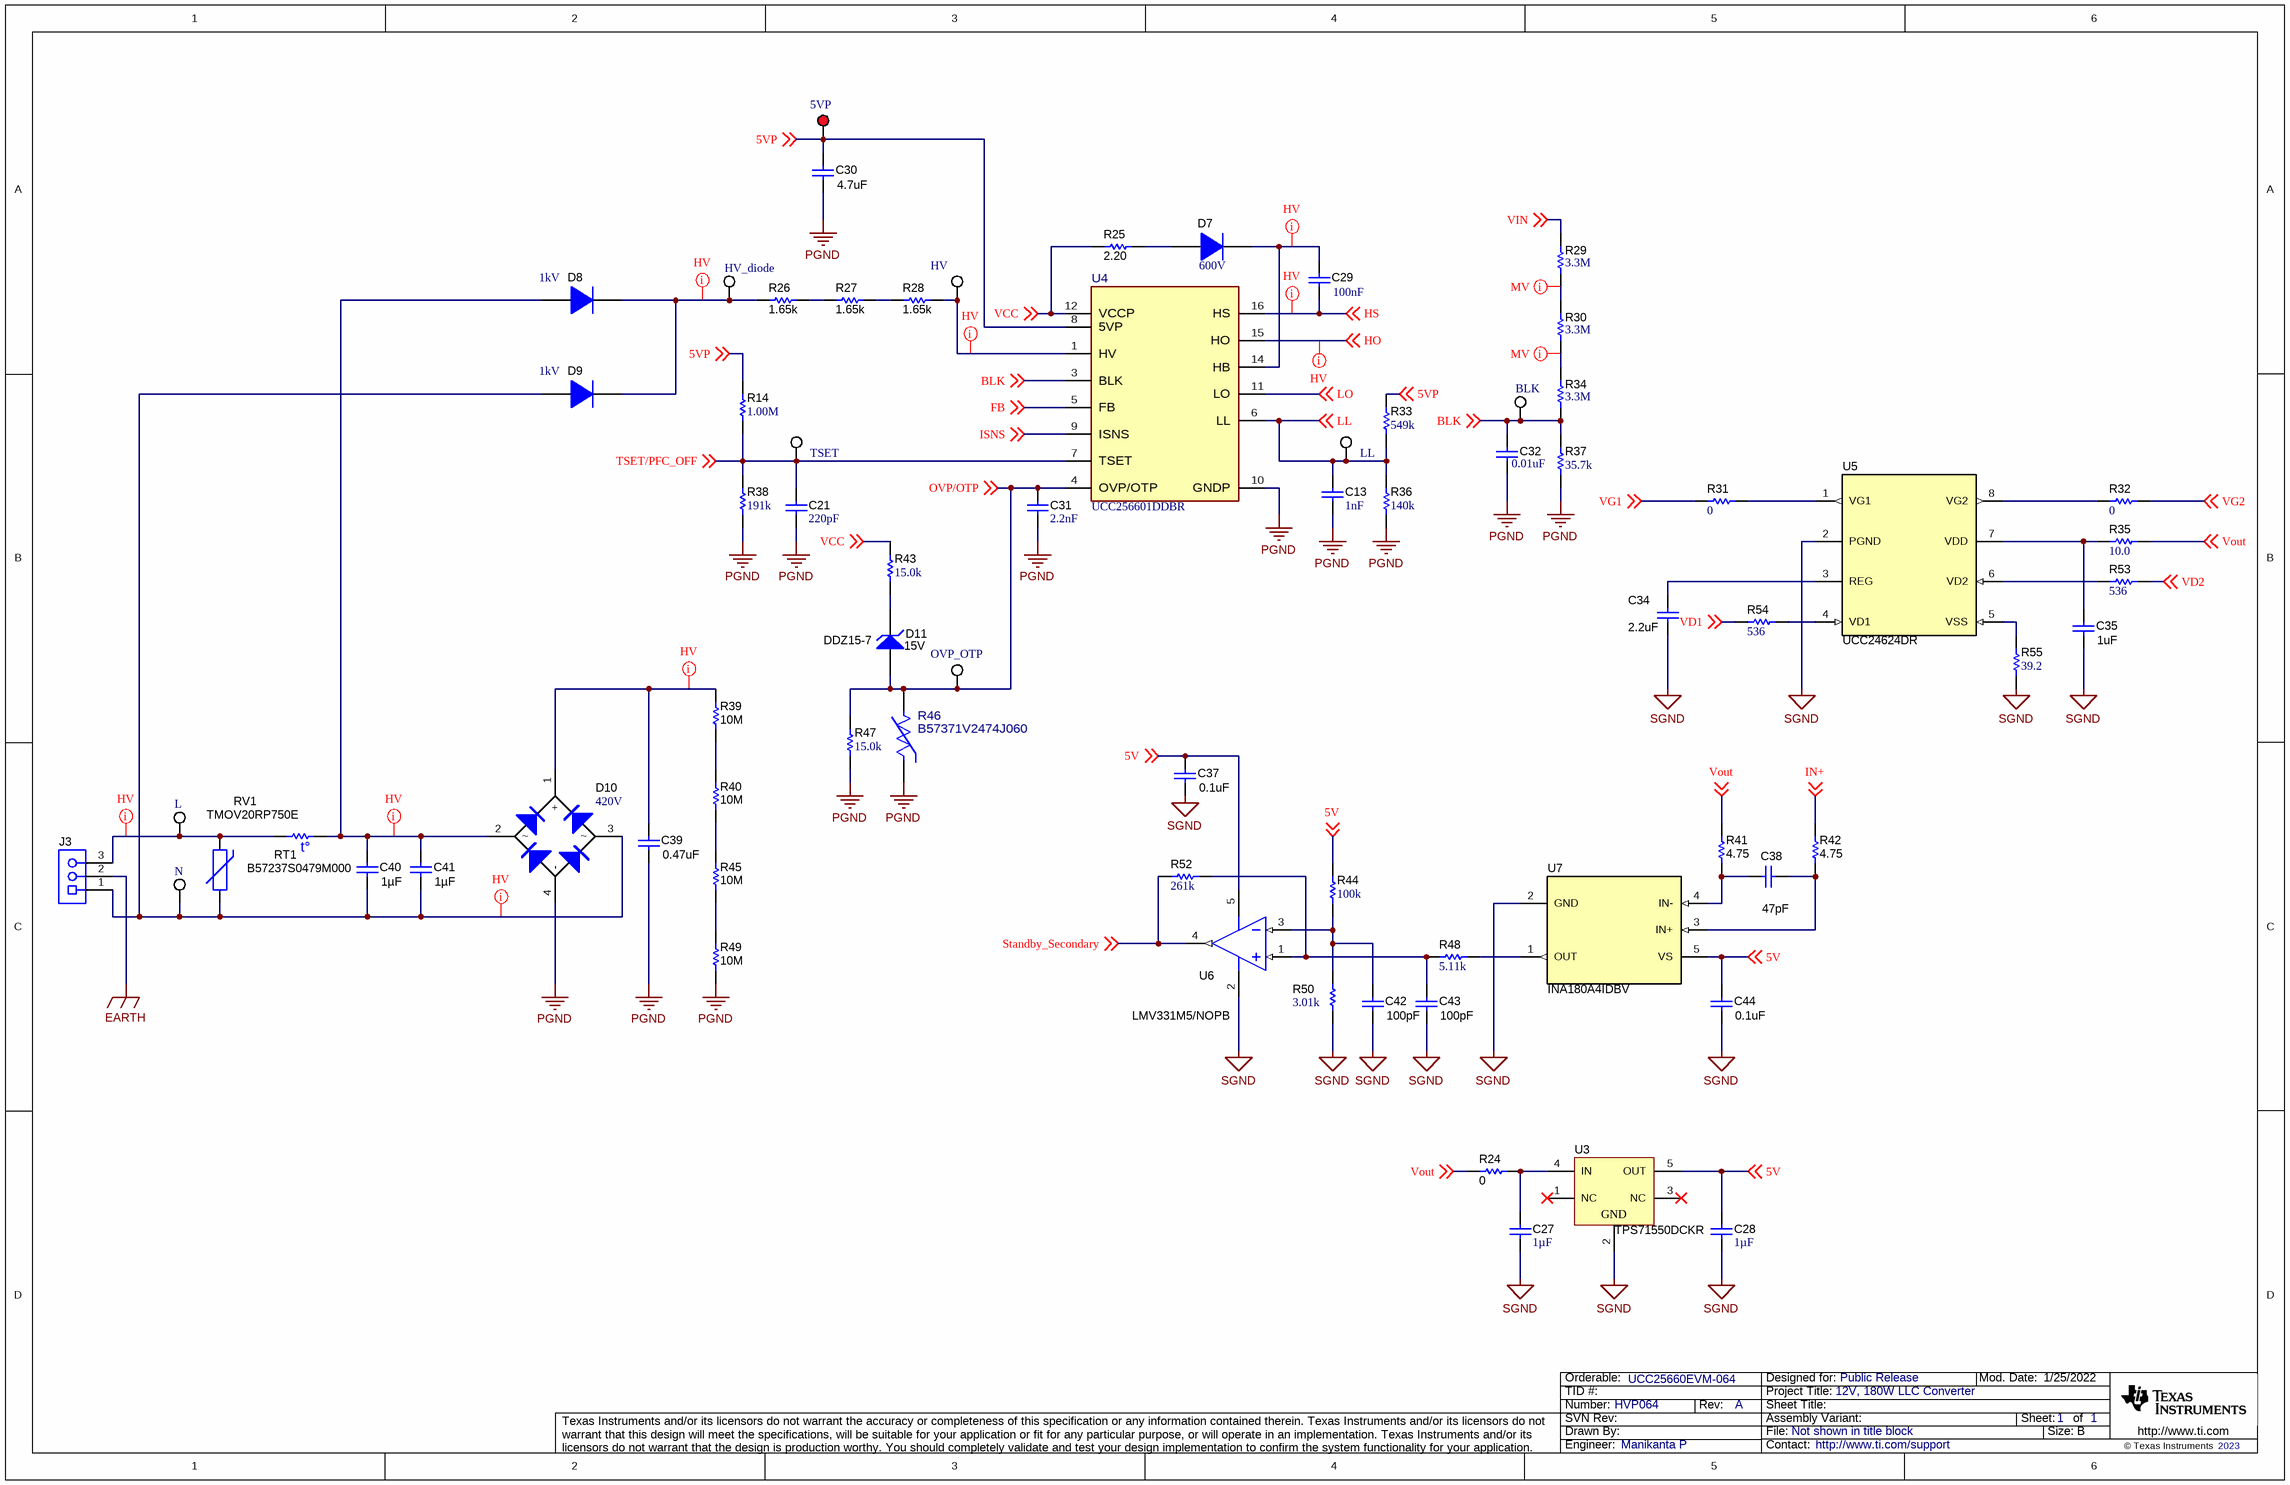
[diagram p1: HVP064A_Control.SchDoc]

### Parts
5VP  5010  [Keystone5010]  (value not drawn)
BLK  5012  [Keystone5012]  (value not drawn)
C13  Cap_F: 1nF  [0603]  (hidden comment: C0603X102K5RACTU)
C21  Cap_F: 220pF  [0603]  (hidden comment: C0603X221K5RACTU)
C27  Cap_F: 1µF  [0603L]  (hidden comment: EMK107B7105KA-T)
C28  Cap_F: 1µF  [0603L]  (hidden comment: EMK107B7105KA-T)
C29  Cap_F: 100nF  [1206_180L]  (hidden comment: GRM31C5C1E104JA01L)
C30  ValueDisplayed: 4.7uF  [1206L]  (hidden comment: C3216X7R1E475K085AB)
C31  Cap_F: 2.2nF  [0603]  (hidden comment: C0603X222K5RACTU)
C32  ValueDisplayed: 0.01uF  [0402L]  (hidden comment: C0402C103J5RACTU)
C34  ValueDisplayed: 2.2uF  [0805L]  (hidden comment: C2012X7R1V225K085AC)
C35  ValueDisplayed: 1uF  [0603L]  (hidden comment: GRM188R71C105KE15D)
C37  ValueDisplayed: 0.1uF  [0402L]  (hidden comment: GRM155R61C104KA88D)
C38  ValueDisplayed: 47pF  [1206L]  (hidden comment: 12067A470JAT2A)
C39  ValueDisplayed: 0.47uF  [B32922_17.5mm]  (hidden comment: B32922C3474K)
C40  ValueDisplayed: 1µF  [R46_2650x1000x1850]  (hidden comment: R46KN410000P0M)
C41  ValueDisplayed: 1µF  [R46_2650x1000x1850]  (hidden comment: R46KN410000P0M)
C42  ValueDisplayed: 100pF  [0402L]  (hidden comment: GRM1555C1H101JA01D)
C43  ValueDisplayed: 100pF  [0402L]  (hidden comment: GRM1555C1H101JA01D)
C44  ValueDisplayed: 0.1uF  [0402L]  (hidden comment: GRM155R61E104KA87D)
D7  Vr_V: 600V  [SMAF]  (hidden comment: ES1JAF)
D8  Vr_V: 1kV  [DO-41]  (hidden comment: 1N4007-E3/73)
D9  Vr_V: 1kV  [DO-41]  (hidden comment: 1N4007-E3/73)
D10  Vr_V: 420V  [GBU]  (hidden comment: GBU8J-BP)
D11  DDZ15-7  value 15V  [SOD-123]
HV  5012  [Keystone5012]  (value not drawn)
HV_diode  5012  [Keystone5012]  (value not drawn)
J3  ED120/3DS  [On-Shore_ED120_3DS]  (value not drawn)
L  5012  [Keystone5012]  (value not drawn)
LL  5012  [Keystone5012]  (value not drawn)
N  5012  [Keystone5012]  (value not drawn)
OVP_OTP  5012  [Keystone5012]  (value not drawn)
R14  ValueDisplayed: 1.00M  [0603]  (hidden comment: RC0603FR-071ML)
R24  ValueDisplayed: 0  [0603L]  (hidden comment: RC0603JR-070RL)
R25  ValueDisplayed: 2.20  [0603L]  (hidden comment: ERJ-3RQF2R2V)
R26  ValueDisplayed: 1.65k  [1206L]  (hidden comment: CRCW12061K65FKEA)
R27  ValueDisplayed: 1.65k  [1206L]  (hidden comment: CRCW12061K65FKEA)
R28  ValueDisplayed: 1.65k  [1206L]  (hidden comment: CRCW12061K65FKEA)
R29  Res_ohm: 3.3M  [FP-KTR18EZPF3304_1206-MFG]  (hidden comment: KTR18EZPF3304)
R30  Res_ohm: 3.3M  [FP-KTR18EZPF3304_1206-MFG]  (hidden comment: KTR18EZPF3304)
R31  ValueDisplayed: 0  [0603L]  (hidden comment: RC0603JR-070RL)
R32  ValueDisplayed: 0  [0603L]  (hidden comment: RC0603JR-070RL)
R33  ValueDisplayed: 549k  [0603]  (hidden comment: RC0603FR-07549KL)
R34  Res_ohm: 3.3M  [FP-KTR18EZPF3304_1206-MFG]  (hidden comment: KTR18EZPF3304)
R35  ValueDisplayed: 10.0  [0603L]  (hidden comment: RC0603FR-0710RL)
R36  ValueDisplayed: 140k  [0603]  (hidden comment: RC0603FR-07140KL)
R37  ValueDisplayed: 35.7k  [0603]  (hidden comment: RT0603BRD0735K7L)
R38  ValueDisplayed: 191k  [0603]  (hidden comment: RT0603BRD07191KL)
R39  ValueDisplayed: 10M  [1206]  (hidden comment: CRCW120610M0JNEA)
R40  ValueDisplayed: 10M  [1206]  (hidden comment: CRCW120610M0JNEA)
R41  ValueDisplayed: 4.75  [0402L]  (hidden comment: CRCW04024R75FKED)
R42  ValueDisplayed: 4.75  [0402L]  (hidden comment: CRCW04024R75FKED)
R43  ValueDisplayed: 15.0k  [0603]  (hidden comment: RG1608P-153-B-T5)
R44  ValueDisplayed: 100k  [0402L]  (hidden comment: ERJ-2RKF1003X)
R45  ValueDisplayed: 10M  [1206]  (hidden comment: CRCW120610M0JNEA)
R46  B57371V2474J060  [FP-B57371V2474J060_0603-MFG]
R47  ValueDisplayed: 15.0k  [0603]  (hidden comment: RG1608P-153-B-T5)
R48  ValueDisplayed: 5.11k  [0402L]  (hidden comment: CRCW04025K11FKED)
R49  ValueDisplayed: 10M  [1206]  (hidden comment: CRCW120610M0JNEA)
R50  ValueDisplayed: 3.01k  [0402L]  (hidden comment: CRCW04023K01FKED)
R52  ValueDisplayed: 261k  [0402L]  (hidden comment: CRCW0402261KFKED)
R53  ValueDisplayed: 536  [0603L]  (hidden comment: RT0603BRD07536RL)
R54  ValueDisplayed: 536  [0603L]  (hidden comment: RT0603BRD07536RL)
R55  ValueDisplayed: 39.2  [0603L]  (hidden comment: RC0603FR-0739R2L)
RT1  B57237S0479M000  [S237]
RV1  TMOV20RP750E  [Littelfuse_TMOV20RP750E]
TSET  5012  [Keystone5012]  (value not drawn)
U3  TPS71550DCKR  [DCK0005A_L]
U4  UCC256601DDBR  [DDB0014A-MFG]
U5  UCC24624DR  [D0008A_N]
U6  LMV331M5/NOPB  [DBV0005A_N]
U7  INA180A4IDBV  [DBV0005A_L]

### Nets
EARTH: J3.2
PGND: C13.2 C21.2 C30.2 C31.2 C32.2 C39.2 D10.4(-) R36.1 R37.1 R38.1 R46.1 R47.1 R49.2 U4.10(GNDP)
SGND: C27.2 C28.2 C34.2 C35.2 C37.2 C42.1 C43.2 C44.2 R50.1 R55.2 U3.2(GND) U5.2(PGND) U6.2(V-) U7.2(GND)
5V: C28.1 C37.1 C44.1 R44.2 U3.5(OUT) U6.5(V+) U7.5(VS) ; off-sheet 5V
5VP: 5VP.1 C30.1 R14.2 R33.2 U4.8(5VP) ; off-sheet 5VP
BLK: BLK.1 C32.1 R34.1 R37.2 U4.3(BLK) ; off-sheet BLK
FB: U4.5(FB) ; off-sheet FB
HO: U4.15(HO) ; off-sheet HO
HS: C29.2 U4.16(HS) ; off-sheet HS
IN+: R42.2 ; off-sheet IN+
ISNS: U4.9(ISNS) ; off-sheet ISNS
LL: C13.1 LL.1 R33.1 R36.2 U4.6(LL) ; off-sheet LL
LO: U4.11(LO) ; off-sheet LO
OVP/OTP: C31.1 D11.2(A) OVP_OTP.1 R46.2 R47.2 U4.4(OVP/OTP) ; off-sheet OVP/OTP
Standby_Secondary: R52.1 U6.4(OUT) ; off-sheet Standby_Secondary
TSET/PFC_OFF: C21.1 R14.1 R38.2 TSET.1 U4.7(TSET) ; off-sheet TSET/PFC_OFF
VCC: R25.1 R43.2 U4.12(VCCP) ; off-sheet VCC
VD1: R54.2 ; off-sheet VD1
VD2: R53.1 ; off-sheet VD2
VG1: R31.1 ; off-sheet VG1
VG2: R32.2 ; off-sheet VG2
VIN: R29.2 ; off-sheet VIN
Vout: R24.1 R35.2 R41.2 ; off-sheet Vout
NetC27_1: C27.1 R24.2 U3.4(IN)
NetC29_1: C29.1 D7.1(K) U4.14(HB)
NetC34_1: C34.1 U5.3(REG)
NetC35_1: C35.1 R35.1 U5.7(VDD)
NetC38_1: C38.1 R41.1 U7.4(IN-)
NetC38_2: C38.2 R42.1 U7.3(IN+)
NetC39_1: C39.1 D10.1(+) R39.1
NetC40_1: C40.1 C41.1 D8.2(A) D10.2 RT1.2
NetC40_2: C40.2 C41.2 D9.2(A) D10.3 J3.1 N.1 RV1.1
NetC42_2: C42.2 R44.1 R50.2 U6.3(IN-)
NetC43_1: C43.1 R48.1 R52.2 U6.1(IN+)
NetD7_2: D7.2(A) R25.2
NetD8_1: D8.1(K) D9.1(K) HV_diode.1 R26.1
NetD11_1: D11.1(K) R43.1
NetHV_1: HV.1 R28.2 U4.1(HV)
NetJ3_3: J3.3 L.1 RT1.1 RV1.2
NetR26_2: R26.2 R27.1
NetR27_2: R27.2 R28.1
NetR29_1: R29.1 R30.2
NetR30_1: R30.1 R34.2
NetR31_2: R31.2 U5.1(VG1)
NetR32_1: R32.1 U5.8(VG2)
NetR39_2: R39.2 R40.1
NetR40_2: R40.2 R45.1
NetR45_2: R45.2 R49.1
NetR48_2: R48.2 U7.1(OUT)
NetR53_2: R53.2 U5.6(VD2)
NetR54_1: R54.1 U5.4(VD1)
NetR55_1: R55.1 U5.5(VSS)

Not connected (* = marked no-connect by the designer): U3 1(NC)* 3(NC)*

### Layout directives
net class MV: NetR29_1, NetR30_1
net class HV: HO, HS, NetC29_1, NetC39_1, NetC40_1, NetC40_2, NetD8_1, NetHV_1, NetJ3_3

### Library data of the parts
5VP = CMP-0055147-2: as VCC on sheet HVP064A_PowerStage
BLK HV HV_diode L LL N OVP_OTP TSET = CMP-0055149-2: as HG on sheet HVP064A_PowerStage
C13 = CMP-0006976-5: CAP, CERM, 1000 pF, 50 V, +/- 10%, X7R, 0603; Manufacturer: Kemet; TaMin_C: -55°C; Polarized: N; SizeAreaWB_mm2: 4.68; Value1: Unknown; U/M: EA; Value: 1000pF; TaMax_C: 125°C; SizeZ_mm: 1; SizeX_mm: 1.6; SizeY_mm: 0.8; Value2: 50V; SizeArea_mm2: 1.28; AEC Category: Q200
C21 = CMP-0006982-4: CAP, CERM, 220 pF, 50 V, +/- 10%, X7R, 0603; Manufacturer: Kemet; TaMin_C: -55°C; Polarized: N; SizeAreaWB_mm2: 4.68; Value1: Unknown; U/M: EA; Value: 220pF; TaMax_C: 125°C; SizeZ_mm: 1; SizeX_mm: 1.6; SizeY_mm: 0.8; Value2: 50V; SizeArea_mm2: 1.28; AEC Category: Q200
C27 C28 = CMP-0007120-4: CAP, CERM, 1 uF, 16 V, +/- 10%, X7R, 0603; Manufacturer: Taiyo Yuden; TaMin_C: -55°C; Polarized: N; SizeAreaWB_mm2: 4.68; Value1: Unknown; U/M: EA; Value: 1uF; TaMax_C: 85°C; SizeZ_mm: 1; SizeX_mm: 1.6; SizeY_mm: 0.8; Cap_Case: 0603; Value2: 16V; SizeArea_mm2: 1.28; AEC Category: Q200
C29 = CMP-0064950-2: CAP, CERM, 0.1 uF, 25 V,+/- 5%, C0G/NP0, 1206; Manufacturer: MuRata; TaMin_C: -55°C; Polarized: N; SizeAreaWB_mm2: 10.92; Value1: Unknown; U/M: EA; Value: 0.1uF; TaMax_C: 125°C; SizeZ_mm: 1.8; SizeX_mm: 3.2; SizeY_mm: 1.6; Cap_Case: 1206; Value2: 25V; SizeArea_mm2: 5.12; AEC Category: Q200
C30 = CMP-0008693-2: CAP, CERM, 4.7 uF, 25 V, +/- 10%, X7R, 1206; Manufacturer: TDK; TaMin_C: -55°C; Polarized: N; SizeAreaWB_mm2: 10.92; Value1: Unknown; U/M: EA; Value: 4.7uF; TaMax_C: 125°C; SizeZ_mm: 1.35; SizeX_mm: 3.2; SizeY_mm: 1.6; Cap_Case: 1206; Value2: 25V; SizeArea_mm2: 5.12; CompType: Capacitor; Cap_F: 4.7µF; AEC Category: Q200
C31 = CMP-0006983-4: CAP, CERM, 2200 pF, 50 V, +/- 10%, X7R, 0603; Manufacturer: Kemet; TaMin_C: -55°C; Polarized: N; SizeAreaWB_mm2: 4.68; Value1: Unknown; U/M: EA; Value: 2200pF; TaMax_C: 125°C; SizeZ_mm: 1; SizeX_mm: 1.6; SizeY_mm: 0.8; Value2: 50V; SizeArea_mm2: 1.28; AEC Category: Q200
C32 = CMP-0006236-2: CAP, CERM, 0.01 uF, 50 V, +/- 5%, X7R, 0402; Manufacturer: Kemet; TaMin_C: -55°C; Polarized: N; SizeAreaWB_mm2: 3; Value1: Unknown; U/M: EA; Value: 0.01uF; TaMax_C: 125°C; SizeZ_mm: 0.6; SizeX_mm: 1; SizeY_mm: 0.5; Cap_Case: 0402; Value2: 50V; Cap_F: 10nF; AEC Category: Q200
C34 = CMP-0007883-2: as C15 on sheet HVP064A_PowerStage
C35 = CMP-0007380-4: CAP, CERM, 1 uF, 16 V, +/- 10%, X7R, 0603; Manufacturer: MuRata; TaMin_C: -55°C; Polarized: N; SizeAreaWB_mm2: 4.68; Value1: Unknown; U/M: EA; Value: 1uF; TaMax_C: 125°C; SizeZ_mm: 1; SizeX_mm: 1.6; SizeY_mm: 0.8; Cap_Case: 0603; Value2: 16V; SizeArea_mm2: 1.28; CompType: Capacitor; Cap_F: 1µF; AEC Category: Q200
C37 = CMP-0006591-2: CAP, CERM, 0.1 uF, 16 V, +/- 10%, X5R, 0402; Manufacturer: MuRata; TaMin_C: -55°C; Polarized: N; SizeAreaWB_mm2: 3; Value1: Unknown; U/M: EA; Value: 0.1uF; TaMax_C: 85°C; SizeZ_mm: 0.6; SizeX_mm: 1; SizeY_mm: 0.5; Cap_Case: 0402; Value2: 16V; CompType: Capacitor; Cap_F: 100nF; AEC Category: Q200
C38 = CMP-0008568-2: CAP, CERM, 47 pF, 500 V, +/- 5%, C0G/NP0, 1206; Manufacturer: AVX; TaMin_C: -55°C; Polarized: N; SizeAreaWB_mm2: 10.92; Value1: Unknown; U/M: EA; Value: 47pF; TaMax_C: 125°C; SizeZ_mm: 1.35; SizeX_mm: 3.2; SizeY_mm: 1.6; Cap_Case: 1206; Value2: 500V; SizeArea_mm2: 5.12; CompType: Capacitor; AEC Category: Q200
C39 = CMP-0012412-3: CAP, Film, 0.47 uF, 630 V, +/- 10%, TH; Manufacturer: TDK; Polarized: N; SizeAreaWB_mm2: 220; Value1: Unknown; Value: 0.47uF; TaMax_C: 110°C; SizeZ_mm: 17.5; SizeX_mm: 18; SizeY_mm: 9; Value2: 630V; SizeArea_mm2: 162; CompType: Capacitor; Cap_F: 470nF; AEC Category: Q200
C40 C41 = CMP-0074805-2: CAP, Film, 1 µF, X2 275 VAC, +/- 20%, TH; Manufacturer: Kemet; TaMin_C: -40°C; Polarized: N; SizeAreaWB_mm2: 342.0; Value: 1uF; TaMax_C: 110°C; VAC_X: 275; SizeZ_mm: 18.6; SizeX_mm: 26.5; SizeY_mm: 10.0; Cap_Case: 26.5x10x18.5mm; Value2: 560V; SizeArea_mm2: 265.0; CompType: Capacitor; AEC Category: Q200
C42 C43 = CMP-0006410-2: CAP, CERM, 100 pF, 50 V, +/- 5%, C0G/NP0, 0402; Manufacturer: MuRata; TaMin_C: -55°C; Polarized: N; SizeAreaWB_mm2: 3; Value1: Unknown; U/M: EA; Value: 100pF; TaMax_C: 125°C; SizeZ_mm: 0.6; SizeX_mm: 1; SizeY_mm: 0.5; Cap_Case: 0402; Value2: 50V; CompType: Capacitor; AEC Category: Q200
C44 = CMP-0006607-2: CAP, CERM, 0.1 uF, 25 V, +/- 10%, X5R, 0402; Manufacturer: MuRata; TaMin_C: -55°C; Polarized: N; SizeAreaWB_mm2: 3; Value1: Unknown; U/M: EA; Value: 0.1uF; TaMax_C: 85°C; SizeZ_mm: 0.6; SizeX_mm: 1; SizeY_mm: 0.5; Cap_Case: 0402; Value2: 25V; CompType: Capacitor; Cap_F: 100nF; AEC Category: Q200
D7 = CMP-0029162-2: Diode, Ultrafast, 600 V, 1 A, AEC-Q101, SMAF; Manufacturer: Fairchild Semiconductor; Io_A: 1A; Green_Lifecycle: Not Set; SizeAreaWB_mm2: 19.95; Green_REACh: Incomplete; TJmax_C: 150°C; Value: 600V; SizeZ_mm: 1; SizeX_mm: 4.7; SizeY_mm: 2.5; Vf_V: 1.7V; SizeArea_mm2: 11.75; AEC Qualified: Y; AEC Category: Q101
D8 D9 = CMP-0029188-2: Diode, P-N, 1000 V, 1 A, TH; Manufacturer: Vishay-Semiconductor; Io_A: 1A; SizeAreaWB_mm2: 43.424; TJmax_C: 150°C; Value: 1000V; SizeZ_mm: 23.4; SizeX_mm: 7.2; SizeY_mm: 2.72; Vf_V: 1.1V; SizeArea_mm2: 19.584; AEC Qualified: N; AEC Category: Q101
D10 = CMP-0029222-3: Diode, Switching-Bridge, 420 V, 8 A, TH; Manufacturer: Micro Commercial Components; Io_A: 8A; Green_Lifecycle: Not Set; SizeAreaWB_mm2: 130.5915; Green_REACh: Incomplete; TJmax_C: 175°C; Value: 420V; SizeZ_mm: 21.55; SizeX_mm: 22.05; SizeY_mm: 3.43; Vf_V: 1V; SizeArea_mm2: 75.6315; AEC Category: Q101
D11 = CMP-0085135-1: Diode, Zener, 15 V, 500 mW, SOD-123; Manufacturer: Diodes Inc.; SizeAreaWB_mm2: 13.095; SizeArea_mm2: 6.545; SizeY_mm: 1.7; AEC Qualified: N; SizeZ_mm: 1.35; Value1: 0.5W; SizeX_mm: 3.85; Power_W: 500mW; RJA_CperW: 425; AEC Category: Q101
J3 = CMP-0074911-1: Terminal Block, 5.08 mm, 3x1, Brass, TH; Manufacturer: On-Shore Technology; Cert_VDE: Y; CNHeader: False; Current_A: 15A; Green_Lifecycle: Not Set; Shrouded: N; Gender: Female; Green_REACh: Incomplete; Voltage_V: 300V; Row_Count: 1; Pitch_mm: 5.08; CT: True
R14 = CMP-0022899-4: RES, 1.00 M, 1%, 0.1 W, 0603; Manufacturer: Yageo; Power_W: 100mW; TempCo: 100 ppm/C; Value_Code: 1M00; Value: 1.00Meg; EIA_Code: E96; Res_ohm: 1M; SizeX_mm: 1.6; SizeY_mm: 0.8; SizeZ_mm: 1; Value2: 0.1W; SizeArea_mm2: 1.28; AEC Qualified: N; VDC_V: 75V; AEC Category: Q200; SizeAreaWB_mm2: 4.68
R24 = CMP-0025885-5: RES, 0, 5%, 0.1 W, 0603; Manufacturer: Yageo; Power_W: 100mW; TempCo: 200 ppm/C; Value_Code: 0000; Value: 0; EIA_Code: E24; SizeX_mm: 1.6; SizeZ_mm: 1; Value2: 0.1W; SizeArea_mm2: 1.28; CompType: Resistor; AEC Qualified: N; VDC_V: 75V; AEC Category: Q200; SizeY_mm: 0.8; SizeAreaWB_mm2: 4.68
R25 = CMP-0022711-2: RES, 2.20, 1%, 0.1 W, 0603; Manufacturer: Panasonic; Power_W: 100mW; TempCo: 200 ppm/C; Value_Code: 2R20; U/M: EA; Value: 2.20; Res_ohm: 2.2; SizeX_mm: 1.6; SizeY_mm: 0.8; SizeZ_mm: 1; Value2: 0.1W; SizeArea_mm2: 1.28; CompType: Resistor; AEC Category: Q200
R26-R28 = CMP-0016708-3: RES, 1.65 k, 1%, 0.25 W, AEC-Q200 Grade 0, 1206; Manufacturer: Vishay-Dale; Power_W: 250mW; TempCo: 100 ppm/C; Value_Code: 1k65; Value: 1.65k; EIA_Code: E96; SizeX_mm: 3.2; SizeY_mm: 1.6; SizeZ_mm: 1.35; Value2: 0.25W; SizeArea_mm2: 5.12; CompType: Resistor; AEC Qualified: Y; VDC_V: 200V; AEC Category: Q200; AEC Grade: 0
R29 R30 R34 = CMP-0087456-2: 3.3 MOhms ±1% 0.25W, 1/4W Chip Resistor 1206 (3216 Metric) Automotive AEC-Q200, High Voltage Thick Film; Manufacturer: Rohm Semiconductor; AEC Qualified: Yes; Power_W: 250mW; SizeZ_mm: 0.65mm; AEC Grade: Grade 0; TempCo: 100ppm/°C; VDC_V: 500V
R31 R32 = CMP-0025885-5: RES, 0, 5%, 0.1 W, 0603; Manufacturer: Yageo; Power_W: 100mW; TempCo: 200 ppm/C; Value_Code: 0000; Value: 0; EIA_Code: E24; SizeX_mm: 1.6; SizeZ_mm: 1; Value2: 0.1W; SizeArea_mm2: 1.28; AEC Qualified: N; VDC_V: 75V; AEC Category: Q200; SizeY_mm: 0.8; SizeAreaWB_mm2: 4.68
R33 = CMP-0023178-4: RES, 549 k, 1%, 0.1 W, 0603; Manufacturer: Yageo; Power_W: 100mW; TempCo: 100 ppm/C; Value: 549k; EIA_Code: E96; SizeX_mm: 1.6; SizeY_mm: 0.8; SizeZ_mm: 1; Value2: 0.1W; SizeArea_mm2: 1.28; AEC Qualified: N; VDC_V: 75V; AEC Category: Q200; SizeAreaWB_mm2: 4.68
R35 = CMP-0022751-4: RES, 10.0, 1%, 0.1 W, 0603; Manufacturer: Yageo; Power_W: 100mW; TempCo: 100 ppm/C; Value_Code: 10R0; Value: 10.0; EIA_Code: E96; Res_ohm: 10; SizeX_mm: 1.6; SizeY_mm: 0.8; SizeZ_mm: 1; Value2: 0.1W; SizeArea_mm2: 1.28; AEC Qualified: N; VDC_V: 75V; AEC Category: Q200; SizeAreaWB_mm2: 4.68
R36 = CMP-0022796-4: RES, 140 k, 1%, 0.1 W, 0603; Manufacturer: Yageo; Power_W: 100mW; TempCo: 100 ppm/C; Value: 140k; EIA_Code: E96; SizeX_mm: 1.6; SizeY_mm: 0.8; SizeZ_mm: 1; Value2: 0.1W; SizeArea_mm2: 1.28; AEC Qualified: N; VDC_V: 75V; AEC Category: Q200; SizeAreaWB_mm2: 4.68
R37 = CMP-0024147-3: RES, 35.7 k, 0.1%, 0.1 W, 0603; Manufacturer: Yageo America; Power_W: 100mW; TempCo: 25 ppm/C; Value_Code: 35k7; U/M: EA; Value: 35.7k; EIA_Code: E192; SizeX_mm: 1.6; SizeY_mm: 0.8; SizeZ_mm: 1; Value2: 0.1W; SizeArea_mm2: 1.28; VDC_V: 75V; AEC Category: Q200
R38 = CMP-0023846-3: RES, 191 k, 0.1%, 0.1 W, 0603; Manufacturer: Yageo America; Power_W: 100mW; TempCo: 25 ppm/C; U/M: EA; Value: 191k; EIA_Code: E192; SizeX_mm: 1.6; SizeY_mm: 0.8; SizeZ_mm: 1; Value2: 0.1W; SizeArea_mm2: 1.28; VDC_V: 75V; AEC Category: Q200
R39 R40 R45 R49 = CMP-0018577-3: RES, 10 M, 5%, 0.25 W, AEC-Q200 Grade 0, 1206; Manufacturer: Vishay-Dale; Power_W: 250mW; TempCo: 200 ppm/C; Value_Code: 10M0; Value: 10Meg; EIA_Code: E24; SizeX_mm: 3.2; SizeY_mm: 1.6; SizeZ_mm: 1.35; Value2: 0.25W; SizeArea_mm2: 5.12; AEC Qualified: Y; VDC_V: 200V; AEC Category: Q200; AEC Grade: 0
R41 R42 = CMP-0026432-2: RES, 4.75, 1%, 0.063 W, AEC-Q200 Grade 0, 0402; Manufacturer: Vishay-Dale; Power_W: 63mW; TempCo: 100 ppm/C; Value_Code: 4R75; Value: 4.75; EIA_Code: E96; SizeX_mm: 1; SizeY_mm: 0.5; SizeZ_mm: 0.6; Value2: 0.063W; CompType: Resistor; AEC Qualified: Y; VDC_V: 50V; AEC Category: Q200; AEC Grade: 0
R43 R47 = CMP-0023441-3: RES, 15.0 k, 0.1%, 0.1 W, 0603; Manufacturer: Susumu Co Ltd; Power_W: 100mW; TempCo: 25 ppm/C; Value_Code: 15k0; U/M: EA; Value: 15.0k; EIA_Code: E192; Res_ohm: 15k; SizeX_mm: 1.6; SizeY_mm: 0.8; SizeZ_mm: 1; Value2: 0.1W; SizeArea_mm2: 1.28; VDC_V: 75V; AEC Category: Q200
R44 = CMP-0026659-2: RES, 100 k, 1%, 0.1 W, 0402; Manufacturer: Panasonic; Power_W: 100mW; TempCo: 100 ppm/C; U/M: EA; Value: 100k; EIA_Code: E96; SizeX_mm: 1; SizeY_mm: 0.5; SizeZ_mm: 0.6; Value2: 0.1W; AEC Qualified: Yes; VDC_V: 50V; AEC Category: Q200; AEC Grade: 0
R46 = CMP-0096703-1: NTC Thermistor 470k 0603 (1608 Metric); Manufacturer: TDK; AEC Qualified: No; Res_ohm: 470kΩ; Power_W: 180mW; B 25 50: 4386K; B 25 100: 4480K; SizeZ_mm: 0.9mm; B 25 85: 4455K; B Tolerance: 3%; Tolerance_%: 5%
R48 = CMP-0026463-2: RES, 5.11 k, 1%, 0.063 W, AEC-Q200 Grade 0, 0402; Manufacturer: Vishay-Dale; Power_W: 63mW; TempCo: 100 ppm/C; Value_Code: 5k11; Value: 5.11k; EIA_Code: E96; SizeX_mm: 1; SizeY_mm: 0.5; SizeZ_mm: 0.6; Value2: 0.063W; AEC Qualified: Y; VDC_V: 50V; AEC Category: Q200; AEC Grade: 0
R50 = CMP-0026329-2: RES, 3.01 k, 1%, 0.063 W, AEC-Q200 Grade 0, 0402; Manufacturer: Vishay-Dale; Power_W: 63mW; TempCo: 100 ppm/C; Value_Code: 3k01; Value: 3.01k; EIA_Code: E96; SizeX_mm: 1; SizeY_mm: 0.5; SizeZ_mm: 0.6; Value2: 0.063W; AEC Qualified: Y; VDC_V: 50V; AEC Category: Q200; AEC Grade: 0
R52 = CMP-0026203-2: RES, 261 k, 1%, 0.063 W, AEC-Q200 Grade 0, 0402; Manufacturer: Vishay-Dale; Power_W: 63mW; TempCo: 100 ppm/C; Value: 261k; EIA_Code: E96; SizeX_mm: 1; SizeY_mm: 0.5; SizeZ_mm: 0.6; Value2: 0.063W; AEC Qualified: Y; VDC_V: 50V; AEC Category: Q200; AEC Grade: 0
R53 R54 = CMP-0024324-2: RES, 536, 0.1%, 0.1 W, 0603; Manufacturer: Yageo America; Power_W: 100mW; TempCo: 25 ppm/C; Value_Code: 536R; U/M: EA; Value: 536; EIA_Code: E192; SizeX_mm: 1.6; SizeY_mm: 0.8; SizeZ_mm: 1; Value2: 0.1W; SizeArea_mm2: 1.28; VDC_V: 75V; AEC Category: Q200
R55 = CMP-0023074-4: RES, 39.2, 1%, 0.1 W, 0603; Manufacturer: Yageo; Power_W: 100mW; TempCo: 100 ppm/C; Value_Code: 39R2; Value: 39.2; EIA_Code: E96; SizeX_mm: 1.6; SizeY_mm: 0.8; SizeZ_mm: 1; Value2: 0.1W; SizeArea_mm2: 1.28; AEC Qualified: N; VDC_V: 75V; AEC Category: Q200; SizeAreaWB_mm2: 4.68
RT1 = CMP-0002554-2: Thermistor NTC, 4.70 ohm, 20%, 15x7mm; Manufacturer: TDK; TaMax_C: 170°C; SizeX_mm: 15; SizeY_mm: 7.5; TaMin_C: -55°C; Power_W: 3.1W; SizeZ_mm: 47; Value: 4.7; SizeArea_mm2: 112.5; SizeAreaWB_mm2: 161.5; U/M: EA
RV1 = CMP-0080568-2: VARISTOR 1200V 10KA DISC 20MM; Manufacturer: Littelfuse; SizeZ_mm: 28; SizeX_mm: 21; SizeY_mm: 13; SizeArea_mm2: 273; SizeAreaWB_mm2: 345
U3 = CMP-0035742-2: Single Output LDO, 50 mA, Fixed 5 V Output, 3 to 24 V Input, 5-pin SC70 (DCK), -40 to 85 degC, Green (RoHS & no Sb/Br); Manufacturer: Texas Instruments; Iq(Typ)(mA): 0.003; Accuracy(%): 4; Vout Adj(Min)(V): 5; SubFamily: Single Channel LDO; Vin(Max)(V): 24; Vin(Min)(V): 3; Vdo(Typ)(mV): 415; Iout(Max)(A): 0.05; AEC Category: Q200; AEC Qualified: N; CompType: IC; SizeAreaWB_mm2: 9.3; SizeArea_mm2: 4.2; SizeX_mm: 2.1; SizeY_mm: 2.0; SizeZ_mm: 1.1
U4 = CMP-0095297-2: 750kHz Wide VIN/VOUT Range LLC Controller Optimized for Light Load Efficiency; Manufacturer: Texas Instruments; TJmax_C: +150°C; AEC Qualified: No; TaMin_C: -40°C; TaMax_C: +125°C; Standoff Height: 0.1mm; Number Of Outputs: 2; Output Type: Other; Switching Frequency: 30-750kHz; Max Supply Voltage: 18.5V; SizeZ_mm: 1.75mm; AEC Category: Q200; CompType: IC
U5 = CMP-0079610-1: High Performance Synchronous Rectifier Driver for LLC Resonant Converter, D0008A (SOIC-8); Alternate Manufacturer: Texas Instruments; SizeAreaWB_mm2: 56.58; SizeZ_mm: 1.75; SizeX_mm: 4.9; SizeY_mm: 6.2; SizeArea_mm2: 30.38; CompType: IC; AEC Qualified: N; AEC Category: Q200
U6 = CMP-0068476-2: Single General Purpose, Low Voltage, Tiny Pack Comparator, 5-pin SOT-23, Pb-Free; Manufacturer: Texas Instruments; PowerWise: Y; PackageTopMarking: C12*XTT; CompType: Amplifiers; AEC Category: Q200; AEC Qualified: N; SizeAreaWB_mm2: 14.82; SizeArea_mm2: 8.12; SizeX_mm: 2.8; SizeY_mm: 2.9; SizeZ_mm: 1.45
U7 = CMP-0013052-2: Low- and High-Side Measurement, Multichannel, Voltage Output, Current-Sense Amplifier, DBV0005A (SOT-5); Manufacturer: Texas Instruments; SizeX_mm: 2.8; SizeY_mm: 2.9; CompType: IC; SizeZ_mm: 1.45; SizeArea_mm2: 8.12; SizeAreaWB_mm2: 14.82; U/M: EA

## Sheet HVP064A_EVM_Hardware.SchDoc
size 431 x 279 mm; Date: Not shown in title block; ApprovedBy: Not shown in title block; CheckedBy: Not shown in title block; Author: Not shown in title block; CompanyName: Not shown in title block; Engineer: Not shown in title block; Organization: Not shown in title block; Address1: Not shown in title block; Address2: Not shown in title block; Address3: Not shown in title block; Address4: Not shown in title block; DocumentNumber: 1; Revision: Use project parameter SCH_Rev; SheetNumber: 1; SheetTotal: 1; PageSetup: Record=PageOptions¦CenterHorizontal=True¦CenterVertical=True¦PrintScale=1.00¦XCorrection=1.00¦YCorrection=1.00¦PrintKind=0¦BorderSize=5000000¦LeftOffset=0¦BottomOffset=0¦Orientation=2¦PaperLength=1000¦PaperWidth=1000¦Scale=100¦PaperSource=15¦PrintQuality=600¦MediaType=1¦DitherType=10¦PaperKind=Letter¦PrintScaleMode=1
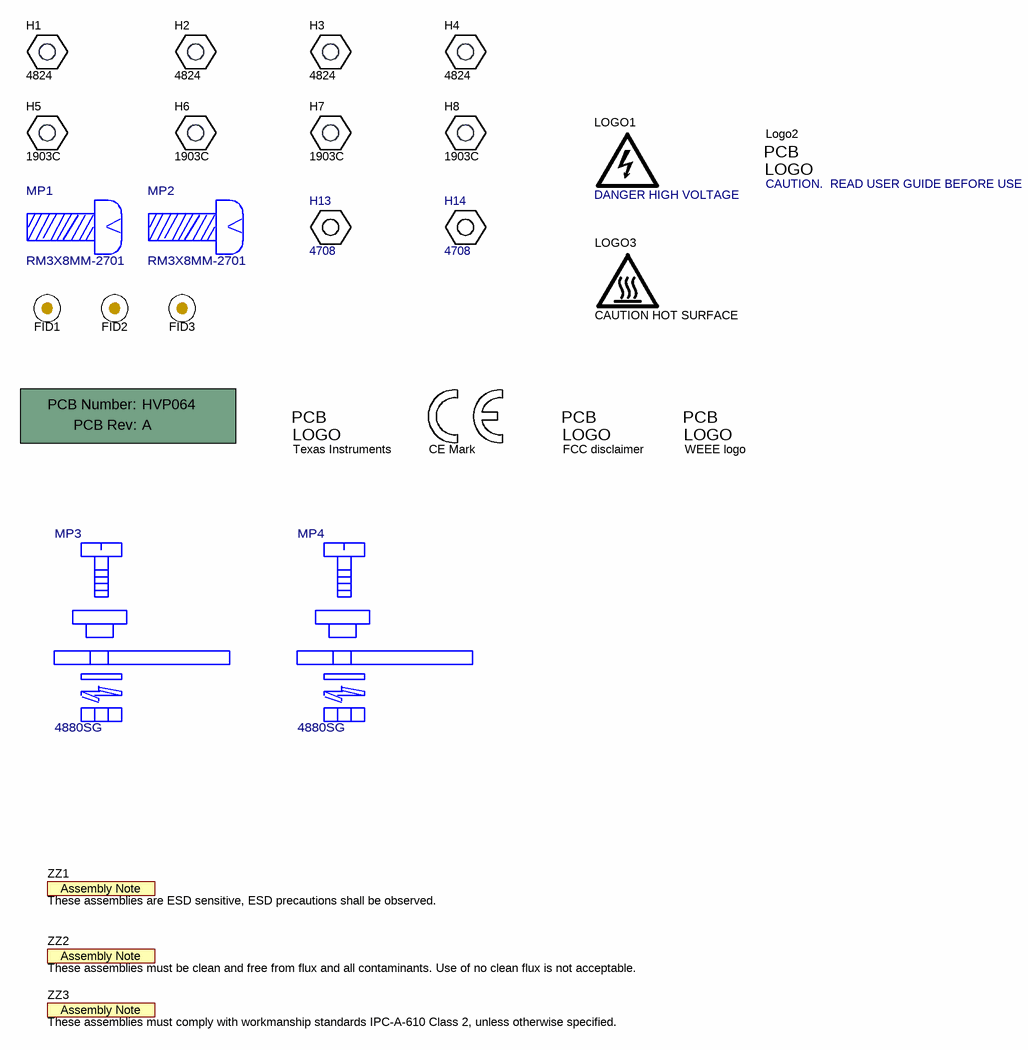
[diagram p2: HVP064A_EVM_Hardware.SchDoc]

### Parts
!PCB1  Printed Circuit Board  (value not drawn)  (mechanical)
FID1  Fiducial  [Fiducial10-20]  (value not drawn)
FID2  Fiducial  [Fiducial10-20]  (value not drawn)
FID3  Fiducial  [Fiducial10-20]  (value not drawn)
H1  4824  [KEYSTONE_4824]
H2  4824  [KEYSTONE_4824]
H3  4824  [KEYSTONE_4824]
H4  4824  [KEYSTONE_4824]
H5  1903C  [KEYSTONE_1903C]
H6  1903C  [KEYSTONE_1903C]
H7  1903C  [KEYSTONE_1903C]
H8  1903C  [KEYSTONE_1903C]
H13  4708  (mechanical)
H14  4708  (mechanical)
LOGO1  DANGER HIGH VOLTAGE  [IEC_HighVoltage_Large]  (no BOM)
Logo2  CAUTION.  READ USER GUIDE BEFORE USE  [IEC_Caution_Large]  (no BOM)
LOGO3  CAUTION HOT SURFACE  [IEC_HotSurface_Large]  (no BOM)
Logo4  CE Mark  [CE_Mark_5mm]  (no BOM)
Logo5  Texas Instruments  [TI_Stacked_Overlay_Small]  (no BOM)
Logo6  FCC disclaimer  [FCC_disclaimer]  (no BOM)
Logo7  WEEE logo  [WEEE_Minimum]  (no BOM)
MP1  RM3X8MM-2701
MP2  RM3X8MM-2701
MP3  4880SG  (mechanical)
MP4  4880SG  (mechanical)
ZZ1  These assemblies are ESD sensitive, ESD precautions shall be observed.  [AssemblyNote]  (no BOM)
ZZ2  These assemblies must be clean and free from flux and all contaminants. Use of no clean flux is not acceptable.  [AssemblyNote]  (no BOM)
ZZ3  These assemblies must comply with workmanship standards IPC-A-610 Class 2, unless otherwise specified.  [AssemblyNote]  (no BOM)

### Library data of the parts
!PCB1 = CMP-0003618-2: Manufacturer: Any; PartNumber: HVP064
FID1-FID3 = CMP-0077181-1: Fiducial mark.  There is nothing to buy or mount.
H1-H4 = CMP-0003690-1: Manufacturer: Keystone; CompType: Standoff
H5-H8 = CMP-0003679-1: Manufacturer: Keystone; CompType: Standoff
H13 H14 = CMP-0003742-1: Manufacturer: Keystone; CompType: Standoff
LOGO1 = CMP-0074835-1: IEC 61010-1 High Voltage Warning; SymbolCreator: a0412235
Logo2 = CMP-0074836-1: IEC 61010-1 Caution Warning; SymbolCreator: a0412235; Lib Reference: IEC_Caution
LOGO3 = CMP-0074837-2: IEC 61010-1 Hot Surface Warning; Manufacturer: Texas Instruments; SymbolCreator: a0412235; AEC Category: Q200; CompType: IC
Logo4 = CMP-0074844-1: SymbolCreator: a0412235
Logo5 = CMP-0074838-1: Texas Instrument Corporate Signature; SymbolCreator: a0412235; Lib Reference: TI_Logo; Library Reference: Logo
Logo6 = CMP-0074847-1: FCC_disclaimer; Library Reference: Logo
Logo7 = CMP-0074769-3: Manufacturer: Texas Instruments; AEC Category: Q200; CompType: IC
MP1 MP2 = CMP-0086732-1: M3 Pan Head Machine Screw Phillips Drive Stainless Steel; Manufacturer: APM Hexseal; Symbol Name: SYM-RM3X8MM-2701
MP3 MP4 = CMP-0087448-2: Mounting Kit For TO-220 Heat Sinks; Manufacturer: Aavid Thermalloy
ZZ1 = CMP-0077236-1
ZZ2 = CMP-0077237-1
ZZ3 = CMP-0077238-1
